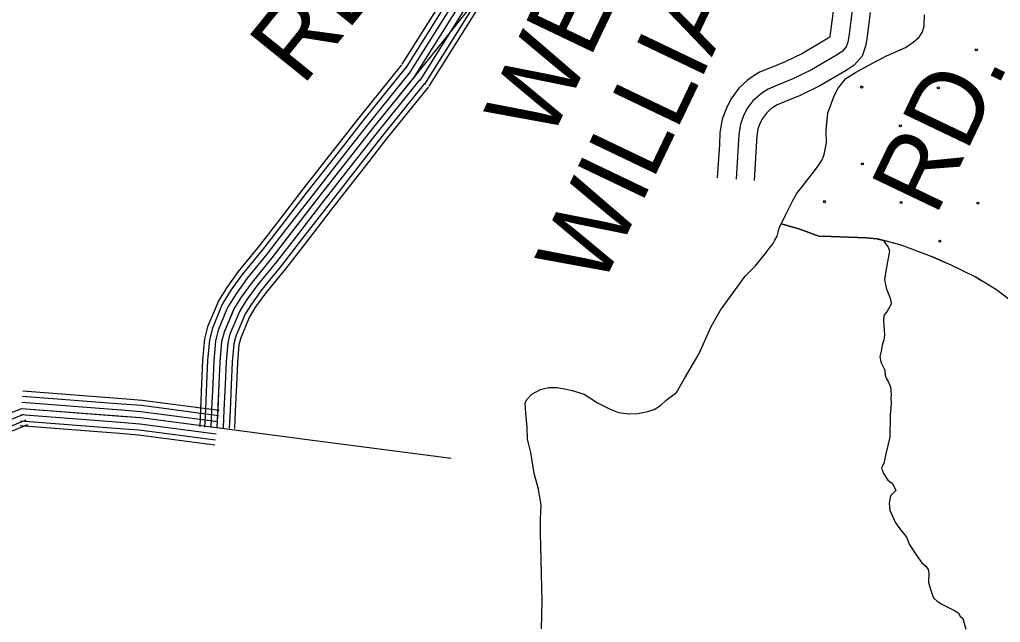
# Model space of a CAD drawing. Extents: x 1551132 to 1791609, y 378168 to 563823.
# Drawn here: x 1596595 to 1601513, y 439720 to 442743 of the extents above; entities that cross this region are included whole.
import ezdxf

# ---------------------------------------------------------------- set-up
doc = ezdxf.new("R2010")
doc.units = 0
for name, color, linetype in [('DESIGN - EROSION CONTROL - Devices', 7, 'Continuous'), ('DESIGN - ROW - Right-of-Way and Easement Labels', 7, 'Continuous'), ('DESIGN - SCRATCH - User 1', 7, 'Continuous'), ('DESIGN - TRANSPORTATION - Text', 7, 'Continuous'), ('SURVEY - PROPERTY - Owners', 7, 'Continuous'), ('SURVEY - TRANSPORTATION - Roads', 7, 'Continuous'), ('SURVEY - VEGETATION - Features with Text', 7, 'Continuous')]:
    doc.layers.add(name, color=color, linetype=linetype)

msp = doc.modelspace()

# ---------------------------------------------------------------- linework, layer by layer
at = {"layer": 'DESIGN - EROSION CONTROL - Devices'}
for centre in [(1601392.535, 442591.343), (1601392.535, 442591.343), (1600817.572, 442404.666), (1600817.572, 442404.666), (1601202.125, 442400.933), (1601202.125, 442400.933), (1601011.715, 442210.523), (1601011.715, 442210.523), (1601396.268, 442206.79), (1601396.268, 442206.79), (1600821.306, 442020.113), (1600821.306, 442020.113), (1601205.859, 442016.38), (1601205.859, 442016.38), (1600630.896, 441829.704), (1600630.896, 441829.704), (1601015.449, 441825.97), (1601015.449, 441825.97), (1601400.002, 441822.237), (1601400.002, 441822.237), (1601209.592, 441631.827), (1601209.592, 441631.827)]:
    msp.add_circle(centre, 5.28, dxfattribs=at)
for centre, start, end in [((1601007.982, 442595.076), 255.264926, 331.246387), ((1601403.735, 441437.684), 14.938145, 102.508661)]:
    msp.add_arc(centre, 5.28, start, end, dxfattribs=at)
at = {"layer": 'DESIGN - SCRATCH - User 1'}
for points in [[(1600588.019, 441993.66), (1600599.685, 442009.019), (1600619.91, 442038.961), (1600630.101, 442066.962), (1600640.484, 442125.039), (1600638.859, 442185.207), (1600648.242, 442274.592), (1600665.767, 442323.369), (1600679.458, 442360.22), (1600700.3, 442399.329), (1600737.874, 442447.864), (1600786.931, 442476.923), (1600853.271, 442514.557), (1600941.711, 442562.067), (1601038.125, 442603.501), (1601076.349, 442629.302), (1601106.557, 442655.153), (1601122.09, 442682.087), (1601130.948, 442711.129), (1601133.306, 442767.256)], [(1600414.372, 441719.178), (1600435.872, 441761.529), (1600472.396, 441835.464), (1600490.637, 441869.423), (1600516.887, 441903.324), (1600569.386, 441969.134), (1600588.019, 441993.66)], [(1600903.319, 441641.584), (1600892.886, 441644.159), (1600840.896, 441648.71), (1600664.825, 441654.543), (1600602.81, 441657.185), (1600503.104, 441694.294), (1600414.372, 441719.178)], [(1604550.783, 440134.381), (1602547.68, 440340.785), (1602224.354, 440723.728), (1601958.544, 441001.218), (1601707.892, 441223.774), (1601493.097, 441387.861), (1601386.308, 441452.73), (1601266.969, 441511.09), (1601158.238, 441558.841), (1601015.033, 441611.892), (1600903.319, 441641.584)]]:
    msp.add_lwpolyline(points, dxfattribs=at)
at = {"layer": 'DESIGN - TRANSPORTATION - Text'}
for points in [[(1599212.883, 439688.707), (1599215.758, 439827.044), (1599211.05, 440033.608), (1599207.9, 440169.986), (1599206.342, 440240.172), (1599210.775, 440308.323), (1599197.259, 440388.617), (1599175.717, 440466.969), (1599158.351, 440571.364), (1599142.752, 440639.649), (1599141.127, 440699.809), (1599133.56, 440770.044), (1599130.502, 440819.895), (1599137.994, 440838.187), (1599164.201, 440864.071), (1599206.417, 440887.839), (1599248.541, 440897.572), (1599290.607, 440897.281), (1599336.631, 440888.939), (1599366.638, 440882.714), (1599426.62, 440864.246), (1599492.452, 440821.679), (1599556.35, 440789.153), (1599598.316, 440772.819), (1599650.356, 440766.436), (1599694.439, 440768.136), (1599744.579, 440777.811), (1599776.695, 440787.611), (1599808.869, 440807.437), (1599837.085, 440835.313), (1599889.409, 440873.047), (1599929.917, 440942.94), (1600002.823, 441068.761), (1600063.772, 441204.689), (1600110.363, 441286.575), (1600170.986, 441370.368), (1600233.627, 441456.146), (1600284.017, 441505.93), (1600334.491, 441567.732), (1600358.74, 441601.65), (1600374.307, 441619.783), (1600383.007, 441637.576), (1600393.148, 441657.559), (1600403.414, 441697.586), (1600435.872, 441761.529), (1600472.396, 441835.464), (1600490.637, 441869.423), (1600516.887, 441903.324), (1600569.386, 441969.134), (1600599.685, 442009.019), (1600619.91, 442038.961), (1600630.101, 442066.962), (1600640.484, 442125.039), (1600638.859, 442185.207), (1600648.242, 442274.592), (1600665.767, 442323.369), (1600679.458, 442360.22), (1600700.3, 442399.329), (1600737.874, 442447.864), (1600786.931, 442476.923), (1600853.271, 442514.557), (1600941.711, 442562.067), (1601038.125, 442603.501), (1601076.349, 442629.302), (1601106.557, 442655.153), (1601122.09, 442682.087), (1601130.948, 442711.129), (1601133.306, 442767.256)], [(1600414.372, 441719.178), (1600503.104, 441694.294), (1600602.81, 441657.185), (1600664.825, 441654.543), (1600840.896, 441648.71), (1600892.886, 441644.159), (1600926.827, 441635.793), (1600934.694, 441621.684), (1600950.51, 441601.475), (1600956.335, 441583.383), (1600937.252, 441473.347), (1600932.893, 441437.321), (1600942.452, 441391.128), (1600956.151, 441358.919), (1600963.918, 441334.793), (1600965.743, 441316.734), (1600945.376, 441280.867), (1600937.26, 441268.925), (1600929.152, 441258.991), (1600926.877, 441230.957), (1600932.218, 441162.764), (1600927.943, 441134.746), (1600921.785, 441118.779), (1600915.41, 441080.77), (1600909.127, 441052.769), (1600912.86, 441024.677), (1600932.518, 440988.401), (1600934.501, 440986.376), (1600936.243, 440960.3), (1600940.093, 440944.233), (1600949.943, 440928.091), (1600957.809, 440913.982), (1600961.692, 440901.915), (1600965.326, 440863.806), (1600963.126, 440843.78), (1600964.892, 440819.713), (1600960.284, 440757.636), (1600959.234, 440649.425), (1600938.401, 440565.465), (1600927.943, 440519.48), (1600917.685, 440493.529), (1600927.435, 440467.379), (1600949.117, 440433.078), (1600970.992, 440418.827), (1600988.65, 440382.568), (1600990.65, 440382.543), (1600962.359, 440354.784), (1600956.001, 440318.775), (1600959.65, 440282.657), (1600985.083, 440222.272), (1601012.724, 440183.905), (1601034.507, 440159.629), (1601046.34, 440141.47), (1601056.073, 440113.311), (1601091.564, 440058.835), (1601119.188, 440018.467), (1601139.046, 440002.225), (1601150.896, 439986.075), (1601154.721, 439967.999), (1601152.254, 439919.923), (1601163.887, 439881.722), (1601175.562, 439847.529), (1601181.487, 439839.454), (1601195.378, 439827.287), (1601219.236, 439811.003), (1601286.959, 439778.236), (1601302.85, 439766.044), (1601310.725, 439751.935), (1601324.617, 439739.768), (1601340.091, 439685.5)]]:
    msp.add_lwpolyline(points, dxfattribs=at)
at = {"layer": 'SURVEY - PROPERTY - Owners'}
for points in [[(1600676.084, 442798.39), (1600659.659, 442671.428), (1600657.184, 442654.836), (1600641.384, 442644.194), (1600520.904, 442573.634), (1600433.939, 442531.816), (1600359.949, 442501.282), (1600305.426, 442478.673), (1600268.943, 442455.897), (1600244.11, 442437.396), (1600202.145, 442398.529), (1600161.037, 442344.402), (1600139.096, 442298.509), (1600117.896, 442243.858), (1600107.105, 442176.465), (1600104.563, 442115.946), (1600093.555, 441948.709)], [(1600769.898, 442788.639), (1600753.048, 442658.419), (1600748.865, 442630.377), (1600740.699, 442606.368), (1600719.966, 442583.434), (1600691.592, 442564.325), (1600565.236, 442490.323), (1600472.388, 442445.672), (1600395.99, 442414.146), (1600348.741, 442394.554), (1600322.167, 442377.962), (1600304.484, 442364.786), (1600272.251, 442334.935), (1600241.952, 442295.043), (1600225.711, 442261.067), (1600209.419, 442219.074), (1600201.078, 442166.998), (1600198.719, 442110.871), (1600187.645, 441942.517)], [(1600860.146, 442779.264), (1600842.888, 442645.902), (1600837.371, 442608.91), (1600820.538, 442559.425), (1600779.823, 442514.382), (1600739.89, 442487.49), (1600607.885, 442410.179), (1600509.371, 442362.803), (1600430.664, 442330.327), (1600390.415, 442313.635), (1600373.365, 442302.993), (1600362.557, 442294.943), (1600339.691, 442273.759), (1600319.792, 442247.558), (1600309.034, 442225.049), (1600297.459, 442195.232), (1600291.484, 442157.889), (1600289.301, 442105.988), (1600278.159, 441936.558)], [(1597584.822, 440696.716), (1598025.345, 440638.548), (1598759.944, 440544.421)]]:
    msp.add_lwpolyline(points, dxfattribs=at)
at = {"layer": 'SURVEY - TRANSPORTATION - Roads'}
for points in [[(1599291.608, 443758.305), (1598511.734, 442518.856)], [(1599314.4, 443748.73), (1598528.676, 442496.255)], [(1599342.974, 443736.722), (1598551.267, 442479.305)], [(1599371.557, 443724.713), (1598573.858, 442456.704)], [(1599400.139, 443712.704), (1598602.099, 442436.92)], [(1599428.714, 443700.696), (1598624.69, 442419.97)], [(1599452.421, 443690.737), (1598647.281, 442408.67)], [(1598873.218, 442829.273), (1598693.222, 442604.15), (1598363.588, 442195.764), (1598084.427, 441839.104), (1597859.849, 441548.172), (1597760.768, 441426.66), (1597706.102, 441350.9), (1597669.612, 441293.048), (1597620.638, 441175.145), (1597608.263, 441127.127), (1597599.513, 441028.95), (1597594.646, 440914.697), (1597584.822, 440696.716)], [(1598510.493, 442515.831), (1598295.706, 442249.724), (1598197.5, 442124.262)], [(1598529.726, 442500.305), (1598315.055, 442234.348), (1598216.958, 442109.028)], [(1598553.842, 442480.838), (1598339.321, 442215.056), (1598241.374, 442089.919)], [(1598577.966, 442461.363), (1598363.588, 442195.764), (1598265.781, 442070.811)], [(1598602.09, 442441.887), (1598387.854, 442176.472), (1598290.189, 442051.702)], [(1598626.207, 442422.42), (1598412.12, 442157.18), (1598314.605, 442032.593)], [(1598646.223, 442406.27), (1598432.253, 442141.179), (1598334.855, 442016.743)], [(1598197.508, 442124.27), (1598015.962, 441892.322), (1597890.065, 441729.226)], [(1598216.966, 442109.037), (1598035.478, 441877.155), (1597909.631, 441714.118)], [(1598241.382, 442089.928), (1598059.953, 441858.13), (1597934.164, 441695.176)], [(1598265.79, 442070.819), (1598084.427, 441839.104), (1597958.705, 441676.233)], [(1598290.198, 442051.71), (1598108.902, 441820.079), (1597983.246, 441657.291)], [(1598314.614, 442032.601), (1598133.376, 441801.053), (1598007.779, 441638.349)], [(1598334.863, 442016.751), (1598153.684, 441785.27), (1598028.137, 441622.632)], [(1597890.073, 441729.243), (1597791.917, 441602.081), (1597691.945, 441479.478), (1597634.204, 441399.451), (1597592.347, 441333.099), (1597582.014, 441308.207)], [(1597909.64, 441714.134), (1597811.275, 441586.714), (1597711.561, 441464.428), (1597654.695, 441385.617), (1597614.371, 441321.682), (1597604.838, 441298.723)], [(1597934.172, 441695.192), (1597835.566, 441567.439), (1597736.168, 441445.544), (1597680.403, 441368.259), (1597641.987, 441307.365), (1597633.462, 441286.84)], [(1597958.713, 441676.25), (1597859.849, 441548.172), (1597760.768, 441426.66), (1597706.102, 441350.9), (1597669.612, 441293.048), (1597662.095, 441274.948)], [(1597983.254, 441657.308), (1597884.132, 441528.905), (1597785.367, 441407.776), (1597731.802, 441333.541), (1597697.236, 441278.731), (1597690.728, 441263.056)], [(1598007.787, 441638.366), (1597908.423, 441509.629), (1597809.975, 441388.892), (1597757.51, 441316.182), (1597724.852, 441264.414), (1597719.352, 441251.172)], [(1598028.145, 441622.649), (1597928.564, 441493.645), (1597830.383, 441373.234), (1597778.834, 441301.79), (1597747.768, 441252.539), (1597743.102, 441241.305)], [(1597582.022, 441308.232), (1597538.198, 441202.737), (1597522.523, 441141.894), (1597512.965, 441034.65), (1597508.015, 440918.497), (1597502.199, 440789.31)], [(1597604.846, 441298.748), (1597561.697, 441194.871), (1597546.956, 441137.686), (1597537.631, 441033.025), (1597532.706, 440917.413), (1597526.89, 440788.202)], [(1597633.479, 441286.856), (1597591.172, 441185.012), (1597577.614, 441132.411), (1597568.572, 441030.983), (1597563.681, 440916.055), (1597557.856, 440786.802)], [(1597662.103, 441274.964), (1597620.638, 441175.145), (1597608.263, 441127.127), (1597599.513, 441028.95), (1597594.646, 440914.697), (1597588.821, 440785.41)], [(1597690.728, 441263.072), (1597650.104, 441165.278), (1597638.912, 441121.844), (1597630.454, 441026.916), (1597625.612, 440913.338), (1597619.787, 440784.018)], [(1597719.36, 441251.181), (1597679.578, 441155.42), (1597669.57, 441116.569), (1597661.395, 441024.875), (1597656.587, 440911.98), (1597650.753, 440782.618)], [(1597743.11, 441241.314), (1597704.027, 441147.236), (1597694.994, 441112.185), (1597687.061, 441023.183), (1597682.278, 440910.855), (1597676.444, 440781.46)], [(1596609.22, 440855.036), (1597107.733, 440816.752)], [(1596611.186, 440880.678), (1597109.699, 440842.394)], [(1597109.683, 440842.403), (1597209.805, 440834.711), (1597596.305, 440783.677)], [(1596425.99, 440720.774), (1596604.47, 440793.218)], [(1596437.765, 440725.558), (1596604.47, 440793.218)], [(1596604.47, 440793.218), (1597200.697, 440747.434), (1597584.822, 440696.716)], [(1596604.47, 440793.218), (1597102.983, 440754.934)], [(1596606.845, 440824.127), (1597105.358, 440785.843)], [(1597105.341, 440785.851), (1597203.914, 440778.276), (1597588.88, 440727.45)], [(1597107.716, 440816.76), (1597207.13, 440809.127), (1597592.938, 440758.184)], [(1597502.199, 440789.335), (1597498.199, 440700.624)], [(1597526.89, 440788.218), (1597522.89, 440699.508)], [(1597557.856, 440786.827), (1597553.856, 440698.116)], [(1597588.821, 440785.427), (1597584.822, 440696.716)], [(1596449.423, 440696.832), (1596616.128, 440764.492)], [(1596602.095, 440762.309), (1597100.608, 440724.025)], [(1597102.966, 440754.942), (1597200.697, 440747.434), (1597584.822, 440696.716)], [(1597619.787, 440784.027), (1597615.787, 440695.316)], [(1597650.753, 440782.635), (1597646.753, 440693.924)], [(1597676.444, 440781.477), (1597672.444, 440692.766)], [(1596461.081, 440668.106), (1596627.786, 440735.766)], [(1596470.373, 440645.206), (1596637.077, 440712.866)], [(1596597.828, 440706.757), (1597096.341, 440668.473)], [(1596599.72, 440731.4), (1597098.233, 440693.116)], [(1597098.216, 440693.124), (1597194.264, 440685.74), (1597576.705, 440635.248)], [(1597100.591, 440724.033), (1597197.481, 440716.591), (1597580.763, 440665.982)], [(1597096.325, 440668.482), (1597191.697, 440661.148), (1597573.472, 440610.747)]]:
    msp.add_lwpolyline(points, dxfattribs=at)
at = {"layer": 'SURVEY - VEGETATION - Features with Text'}
for points in [[(1600588.019, 441993.66), (1600599.685, 442009.019), (1600619.91, 442038.961), (1600630.101, 442066.962), (1600640.484, 442125.039), (1600638.859, 442185.207), (1600648.242, 442274.592), (1600665.767, 442323.369), (1600679.458, 442360.22), (1600700.3, 442399.329), (1600737.874, 442447.864), (1600786.931, 442476.923), (1600853.271, 442514.557), (1600941.711, 442562.067), (1601038.125, 442603.501), (1601076.349, 442629.302), (1601106.557, 442655.153), (1601122.09, 442682.087), (1601130.948, 442711.129), (1601133.306, 442767.256)], [(1600900.47, 442539.916), (1600941.711, 442562.067), (1601038.125, 442603.501), (1601076.349, 442629.302), (1601106.557, 442655.153), (1601119.732, 442677.995)], [(1600692.9, 442385.437), (1600700.3, 442399.329), (1600737.874, 442447.864), (1600786.931, 442476.923), (1600853.271, 442514.557), (1600900.478, 442539.916)], [(1600588.019, 441993.66), (1600599.685, 442009.019), (1600619.91, 442038.961), (1600630.101, 442066.962), (1600640.484, 442125.039), (1600638.859, 442185.207), (1600645.084, 442244.475)], [(1600414.372, 441719.178), (1600435.872, 441761.529), (1600472.396, 441835.464), (1600490.637, 441869.423), (1600516.887, 441903.324), (1600569.386, 441969.134), (1600588.019, 441993.66)], [(1600414.372, 441719.178), (1600435.872, 441761.529), (1600472.396, 441835.464), (1600490.637, 441869.423), (1600516.887, 441903.324), (1600549.703, 441944.459)], [(1600414.372, 441719.178), (1600503.104, 441694.294), (1600602.81, 441657.185), (1600664.825, 441654.543), (1600840.896, 441648.71), (1600892.886, 441644.159), (1600903.319, 441641.584)], [(1600414.372, 441719.178), (1600503.104, 441694.294), (1600602.81, 441657.185), (1600664.825, 441654.543), (1600668.208, 441654.435)], [(1600818.121, 441649.468), (1600840.896, 441648.71), (1600892.886, 441644.159), (1600903.319, 441641.584)], [(1604764.486, 440113.163), (1602547.68, 440340.785), (1602224.354, 440723.728), (1601958.544, 441001.218), (1601707.892, 441223.774), (1601493.097, 441387.861), (1601386.308, 441452.73), (1601266.969, 441511.09), (1601158.238, 441558.841), (1601015.033, 441611.892), (1600903.319, 441641.584)], [(1601183.929, 441547.557), (1601158.238, 441558.841), (1601015.033, 441611.892), (1600934.61, 441633.268)], [(1601420.882, 441431.729), (1601386.308, 441452.73), (1601266.969, 441511.09), (1601183.921, 441547.557)]]:
    msp.add_lwpolyline(points, dxfattribs=at)

# ---------------------------------------------------------------- texts
at = {"layer": 'DESIGN - ROW - Right-of-Way and Easement Labels'}
for s, height, rotation, p in [('WILLIAMS', 370.0064, 64.447744, (1599508.194, 441386.86)), ('WEBB', 370.0064, 64.447744, (1599251.9, 442121.629)), ('RD.', 370.0027, 51.091467, (1598013.663, 442404.994)), ('RD.', 370.0064, 64.447744, (1601188.463, 441751.804))]:
    msp.add_text(s, height=height, rotation=rotation, dxfattribs=at).set_placement(p)

doc.saveas('drawing.dxf')
